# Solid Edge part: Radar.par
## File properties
Author: Egon 815
Template: Normal.par
Last saved by: Egon 815
Revision: 6
Application: Solid Edge
Accuracy: 0,990
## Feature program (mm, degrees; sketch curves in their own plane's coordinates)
lofted protrusion "unnamed LoftedProtrusion 1"
sketch for "ExtrudedProtrusion_3" plane through (0, 37412.0553, 21758.8218) normal (0, 0, 1) x-axis (1, 0, 0)
  circle centre (0, 48.2951) radius 2406.4213
extrude "ExtrudedProtrusion_3" add finite 6000 symmetric
sketch for "ExtrudedProtrusion_4" #1 plane through (0, 37412.0553, 21758.8218) normal (0, 0, 1) x-axis (1, 0, 0)
  circle centre (-1634.7093, -1717.6577) radius 1068.4922
sketch for "ExtrudedProtrusion_4" #2 plane through (0, 37412.0553, 21758.8218) normal (0, 0, 1) x-axis (1, 0, 0)
  circle centre (-1359.1081, 1112.0454) radius 1359.1081
sketch for "ExtrudedProtrusion_4" #3 plane through (0, 37412.0553, 21758.8218) normal (0, 0, 1) x-axis (1, 0, 0)
  circle centre (1972.1702, 1427.2108) radius 894.4327
extrude "ExtrudedProtrusion_4" add finite 4000 symmetric
sketch for "ExtrudedProtrusion_5" #1 plane through (0, 37412.0553, 21758.8218) normal (0, 0, 1) x-axis (1, 0, 0)
  circle centre (1634.7093, -1717.6577) radius 1161.1557
sketch for "ExtrudedProtrusion_5" #2 plane through (0, 37412.0553, 21758.8218) normal (0, 0, 1) x-axis (1, 0, 0)
  circle centre (-2237.5247, 789.0536) radius 602.8154
extrude "ExtrudedProtrusion_5" add finite 3000 symmetric
sketch for "ExtrudedProtrusion_6" #1 plane through (0, 37412.0553, 21758.8218) normal (0, 0, 1) x-axis (1, 0, 0)
  circle centre (630.4554, -2300.5443) radius 1731.2477
sketch for "ExtrudedProtrusion_6" #2 plane through (0, 37412.0553, 21758.8218) normal (0, 0, 1) x-axis (1, 0, 0)
  circle centre (-1658.1305, 569.2966) radius 619.6698
extrude "ExtrudedProtrusion_6" add finite 2500 symmetric
sketch for "ExtrudedProtrusion_7" plane through (0, 0, 0) normal (1, 0, 0) x-axis (0, 1, 0)
  arc centre (35713.1973, 27398.608) radius 1500 from (36382.763, 28740.8754) to (36386.9464, 26058.4355) cw
  line (38489.2299, 26058.4355) -> (36386.9464, 26058.4355)
  arc centre (39176.7102, 27391.6162) radius 1500 from (38489.2299, 26058.4355) to (38521.348, 28740.8754) cw
  line (36382.763, 28740.8754) -> (38521.348, 28740.8754)
extrude "ExtrudedProtrusion_7" add finite 10000 symmetric
thinwall "Thinwall_2"  Thickness = 20 mm
sketch for "unnamed Protrusion 1" plane through (0, 37460.3503, 24758.8218) normal (0, 0, 1) x-axis (0, 1, 0)
  circle centre (-16.6633, -5.9208) radius 218.8582
extrude "unnamed Protrusion 1" add to key point along +normal
chamfer "Chamfer_1" setback 100
chamfer "Chamfer_2" setback 50
sketch for "ExtrudedProtrusion_10" plane through (0, 37412.0553, 7204.8312) normal (0, 0, 1) x-axis (-1, 0, 0)
  line (-8024.1893, -3100.8716) -> (-8024.1893, 4560.6801)
  line (-8024.1893, 4560.6801) -> (-65.1566, 4560.6801)
  line (-65.1566, 4560.6801) -> (-65.1566, -3100.8716)
  line (-65.1566, -3100.8716) -> (-8024.1893, -3100.8716)
extrude "ExtrudedProtrusion_10" add finite 3000 along +normal
chamfer "Chamfer_3" setback 200
lofted protrusion "unnamed LoftedProtrusion 2"
chamfer "Chamfer_4" setback 1000
sketch for "unnamed Protrusion 2" plane through (0, 37412.0553, 21758.8218) normal (0, 0, 1) x-axis (1, 0, 0)
  circle centre (630.4554, -2300.5443) radius 1731.2477
extrude "unnamed Protrusion 2" add to key point along -normal
Other named dimensions: "ExtrudedSurface_1": FiniteDepth = 2064.5045 mm
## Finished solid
Body 1: sheet body, 4 faces, 12 edges, 8 vertices.
  Faces by surface: cylinder 2, plane 2
  Edges by curve: line 8, circle 4
Body 2: solid body, 82 faces, 211 edges, 136 vertices, 1 internal void.
  Faces by surface: plane 45, cylinder 19, cone 13, spline 5
  Edges by curve: line 89, circle 73, intersection 31, ellipse 10, curve on surface 8
Bounding box of the edges (mm; curved faces can reach further): 14080.693 x 7661.552 x 21556.044, from (-6056.5039, 32851.3752, 7184.8312) to (8024.1893, 40512.9268, 28740.8754).
Cylindrical faces by radius (mm): R218.8582 x1, R582.8154 x1, R602.8154 x1, R874.4327 x1, R894.4327 x1, R1048.4922 x1, R1068.4922 x1, R1141.1557 x1, R1161.1557 x1, R1339.1081 x1, R1359.1081 x1, R1500 x4, R1520 x2, R1711.2477 x1, R1731.2477 x1, R2386.4213 x1, R2406.4213 x1
Conical faces (half-angle, radius in mm at the cone's reference point): 45 deg R268.8582 x1, 45 deg R602.8154 x1, 45 deg R894.4327 x1, 45 deg R1068.4922 x1, 45 deg R1161.1557 x1, 45 deg R1359.1081 x1, 45 deg R1731.2477 x1, 45 deg R2406.4213 x6
Planar faces by outward normal: +x 3, +y 1, +z 14, -x 4, -y 1, -z 11, oblique 11
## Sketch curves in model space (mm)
line (8024.1893, 32851.3752, 7204.8312) -> (65.1566, 32851.3752, 7204.8312)
line (65.1566, 32851.3752, 7204.8312) -> (65.1566, 40512.9268, 7204.8312)
line (65.1566, 40512.9268, 7204.8312) -> (8024.1893, 40512.9268, 7204.8312)
line (8024.1893, 40512.9268, 7204.8312) -> (8024.1893, 32851.3752, 7204.8312)
circle centre (5.9208, 37443.687, 24758.8218) radius 218.8582
line (0, 36382.763, 28740.8754) -> (0, 38521.348, 28740.8754)
arc centre (0, 35713.1973, 27398.608) radius 1500 from (0, 36382.763, 28740.8754) through (0, 37212.5947, 27356.0939) to (0, 36386.9464, 26058.4355)
line (0, 38489.2299, 26058.4355) -> (0, 36386.9464, 26058.4355)
arc centre (0, 39176.7102, 27391.6162) radius 1500 from (0, 38489.2299, 26058.4355) through (0, 37678.0257, 27454.422) to (0, 38521.348, 28740.8754)
circle centre (-1658.1305, 37981.3518, 21758.8218) radius 619.6698
circle centre (0, 37460.3503, 21758.8218) radius 2406.4213
circle centre (-1359.1081, 38524.1007, 21758.8218) radius 1359.1081
circle centre (-2237.5247, 38201.1089, 21758.8218) radius 602.8154
circle centre (-1634.7093, 35694.3975, 21758.8218) radius 1068.4922
circle centre (1634.7093, 35694.3975, 21758.8218) radius 1161.1557
circle centre (630.4554, 35111.511, 21758.8218) radius 1731.2477
circle centre (1972.1702, 38839.2661, 21758.8218) radius 894.4327
line (3357.0023, 40249.8685, 21758.8218) -> (0, 40249.8685, 21758.8218)
arc centre (3357.0023, 37413.2477, 21758.8218) radius 2836.6209 from (3357.0023, 40249.8685, 21758.8218) through (6192.3774, 37329.1892, 21758.8218) to (3357.0023, 34576.6268, 21758.8218)
line (3357.0023, 34576.6268, 21758.8218) -> (0, 34576.6268, 21758.8218)
line (-3357.0023, 34576.6268, 21758.8218) -> (0, 34576.6268, 21758.8218)
arc centre (-3357.0023, 37413.2477, 21758.8218) radius 2836.6209 from (-3357.0023, 40249.8685, 21758.8218) through (-6192.3774, 37329.1892, 21758.8218) to (-3357.0023, 34576.6268, 21758.8218)
line (-3357.0023, 40249.8685, 21758.8218) -> (0, 40249.8685, 21758.8218)
line (-4176.1952, 34852.7254, 7184.8312) -> (0, 34852.7254, 7184.8312)
line (4176.1952, 34852.7254, 7184.8312) -> (0, 34852.7254, 7184.8312)
line (4176.1952, 39971.3851, 7184.8312) -> (4176.1952, 34852.7254, 7184.8312)
line (4176.1952, 39971.3851, 7184.8312) -> (0, 39971.3851, 7184.8312)
line (-4176.1952, 39971.3851, 7184.8312) -> (0, 39971.3851, 7184.8312)
line (-4176.1952, 39971.3851, 7184.8312) -> (-4176.1952, 34852.7254, 7184.8312)
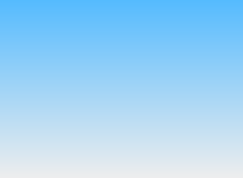
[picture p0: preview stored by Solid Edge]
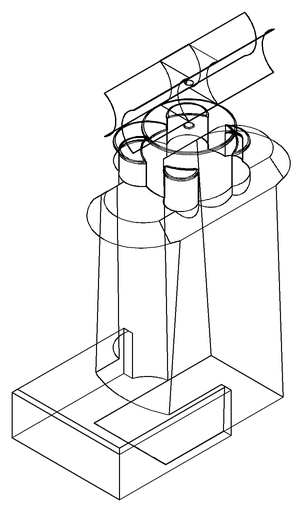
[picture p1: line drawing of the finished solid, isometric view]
